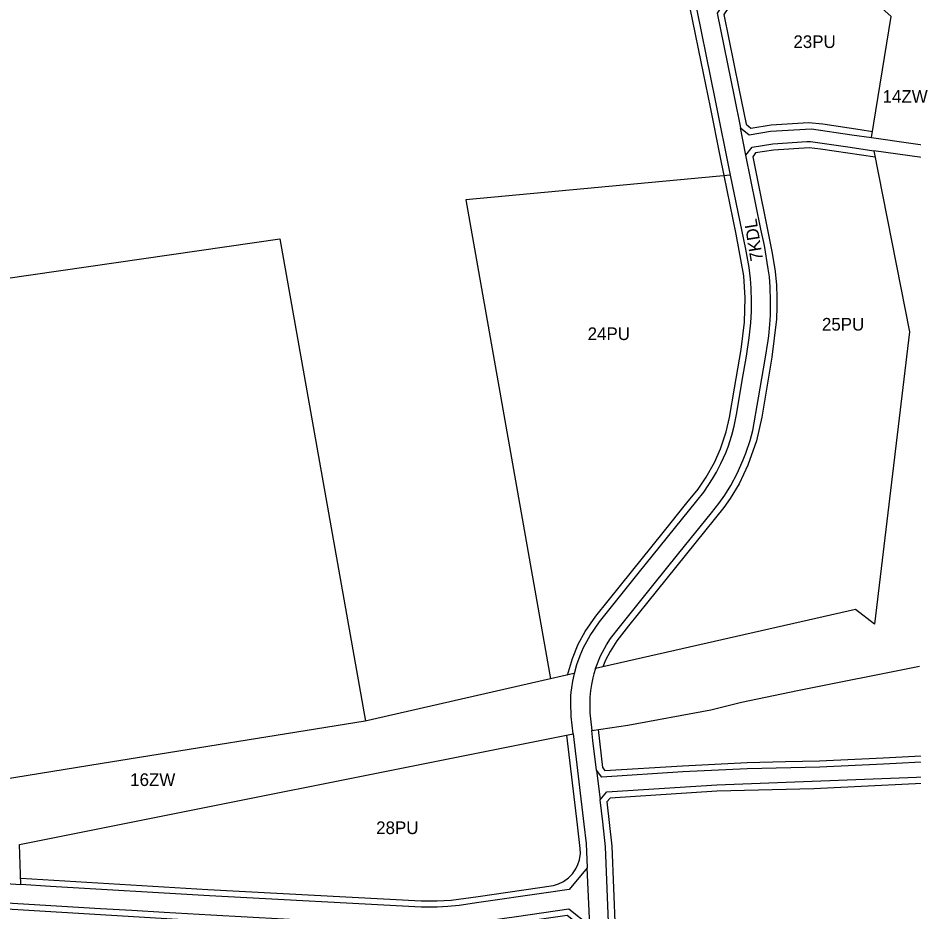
# Model space of a CAD drawing. Extents: x 7428203 to 7432868, y 5542672 to 5545406.
# Drawn here: x 7429895 to 7430602, y 5543859 to 5544564 of the extents above; entities that cross this region are included whole.
import ezdxf

# ---------------------------------------------------------------- set-up
doc = ezdxf.new("R2010")
doc.units = 0
for name, color, linetype in [('linie_rozgraniczajace', 7, 'Continuous'), ('linie_zabudowy_nieprzekraczalne', 7, 'Continuous'), ('oznaczenia_przeznaczen', 7, 'Continuous')]:
    doc.layers.add(name, color=color, linetype=linetype)

msp = doc.modelspace()

# ---------------------------------------------------------------- linework, layer by layer
at = {"layer": 'linie_rozgraniczajace'}
for p, q in [((7430635.44, 5544449.92), (7430571.27, 5544459.14)), ((7430571.27, 5544459.14), (7430599.39, 5544316.2)), ((7430599.39, 5544316.2), (7430571.63, 5544085.3)), ((7430556.6, 5544096.8), (7430351.39, 5544050.23)), ((7430571.63, 5544085.3), (7430556.6, 5544096.8)), ((7430351.39, 5544050.23), (7430350.06, 5544045.98)), ((7430510.83, 5544032.94), (7430607.17, 5544051.99)), ((7430349.25, 5544042.86), (7430348.11, 5544037.51)), ((7430350.06, 5544045.98), (7430349.25, 5544042.86)), ((7430348.11, 5544037.51), (7430347.39, 5544032.85)), ((7430346.86, 5544027.65), (7430346.66, 5544022.69)), ((7430347.39, 5544032.85), (7430346.86, 5544027.65)), ((7430466.5, 5544023.7), (7430510.83, 5544032.94)), ((7430346.66, 5544022.69), (7430346.83, 5544015.27)), ((7430442.42, 5544017.56), (7430466.5, 5544023.7)), ((7430346.83, 5544015.27), (7430347.24, 5544010.35)), ((7430376.69, 5544005.34), (7430442.42, 5544017.56)), ((7430347.24, 5544010.35), (7430348.32, 5544001.36)), ((7430348.32, 5544001.36), (7430376.69, 5544005.34)), ((7430349.26, 5543993.46), (7430348.32, 5544001.36)), ((7430352.08, 5543970), (7430349.26, 5543993.46)), ((7430471.2, 5543970.94), (7430420.25, 5543968.49)), ((7430528.46, 5543972.27), (7430471.2, 5543970.94)), ((7430578.76, 5543974.63), (7430528.46, 5543972.27)), ((7430631.1, 5543977.3), (7430578.76, 5543974.63)), ((7430356.31, 5543964.43), (7430352.08, 5543970)), ((7430352.08, 5543970), (7430354.92, 5543946.37)), ((7430420.25, 5543968.49), (7430356.31, 5543964.43)), ((7430447, 5543958.42), (7430641.3, 5543965.87)), ((7430360.29, 5543952.75), (7430447, 5543958.42)), ((7430354.92, 5543946.37), (7430360.29, 5543952.75)), ((7430357, 5543929.02), (7430354.92, 5543946.37)), ((7430359.23, 5543909.49), (7430357, 5543929.02)), ((7430361.88, 5543843.19), (7430359.23, 5543909.49))]:
    msp.add_line(p, q, dxfattribs=at)
for points in [[(7430457.97, 5544439.94), (7430446.05, 5544498.9), (7430427.95, 5544588.48), (7430420.35, 5544625.11)], [(7430470.09, 5544455.7), (7430465.74, 5544477.21), (7430472.67, 5544471.8), (7430489.65, 5544474.52), (7430521.79, 5544476.48), (7430553.88, 5544471.74), (7430569.42, 5544469.51), (7430584.87, 5544565.16), (7430563.07, 5544584.92), (7430554.24, 5544583.75), (7430532.74, 5544581.22), (7430519.71, 5544580.53), (7430493.95, 5544579.21), (7430453.82, 5544577.48), (7430447.41, 5544567.9), (7430460.75, 5544501.87), (7430465.74, 5544477.21)], [(7430351.39, 5544050.23), (7430355.34, 5544060.32), (7430359.99, 5544068.89), (7430363.09, 5544073.8), (7430370.17, 5544082.89), (7430396.63, 5544115.75), (7430417.17, 5544141.27), (7430442.92, 5544173.26), (7430448.83, 5544180.6), (7430453.44, 5544187.22), (7430458.17, 5544194.87), (7430463.17, 5544204.14), (7430468.02, 5544214.93), (7430470.1, 5544220.23), (7430473.42, 5544230.29), (7430475.46, 5544238.15), (7430480.04, 5544263.9), (7430485.31, 5544294.55), (7430487.59, 5544309.3), (7430488.1, 5544313.04), (7430489, 5544321.97), (7430489.45, 5544329.17), (7430489.61, 5544335.11), (7430489.63, 5544340.5), (7430489.24, 5544351.51), (7430488.61, 5544359.44), (7430487.81, 5544365.89), (7430484.66, 5544384.16), (7430481.93, 5544397.12), (7430470.09, 5544455.7), (7430475.05, 5544462.06), (7430491.42, 5544464.62), (7430518.2, 5544466.48), (7430521.12, 5544466.48), (7430552.43, 5544461.85), (7430571.27, 5544459.14)], [(7430569.42, 5544469.51), (7430633.38, 5544460.3)], [(7430334.65, 5544046.29), (7430336.64, 5544053.5), (7430339.05, 5544060.42), (7430341.77, 5544066.74), (7430346.97, 5544076.34), (7430354.31, 5544087.15), (7430384.94, 5544125.16), (7430431.24, 5544182.66), (7430436.82, 5544189.6), (7430440.93, 5544195.5), (7430443.69, 5544199.89), (7430446.9, 5544205.38), (7430448.26, 5544207.93), (7430450.4, 5544212.15), (7430452.42, 5544216.56), (7430454.14, 5544220.61), (7430455.99, 5544225.32), (7430459.03, 5544234.53), (7430460.84, 5544241.52), (7430462.71, 5544250.78), (7430465.24, 5544266.38), (7430467.2, 5544277.74), (7430470.5, 5544296.91), (7430472.75, 5544311.46), (7430474.05, 5544323.19), (7430474.54, 5544332.24), (7430474.63, 5544340.19), (7430474.27, 5544350.65), (7430473.69, 5544357.92), (7430472.56, 5544367.02), (7430469.94, 5544381.26), (7430457.97, 5544439.94), (7430248.78, 5544420.45), (7430315.6, 5544041.93)], [(7429810.29, 5543885.43), (7429897.37, 5543879.68), (7429896.16, 5543911.28), (7430333.54, 5543998.57), (7430332, 5544012.38), (7430331.66, 5544022.98), (7430331.89, 5544028.62), (7430332.14, 5544031.45), (7430332.52, 5544034.83), (7430333.36, 5544040.22), (7430334.65, 5544046.29), (7430334.23, 5544046.17), (7430315.6, 5544041.93), (7430169.18, 5544008.59), (7429959.79, 5543974.93), (7429805.3, 5543949.82)], [(7430333.54, 5543998.57), (7430342.1, 5543927.28), (7430343.85, 5543911.94), (7430344.79, 5543892.69), (7430330.57, 5543875.57), (7430310.52, 5543872.69), (7430259.19, 5543865.33), (7430243.57, 5543863.06), (7430234.64, 5543862.21), (7430226.25, 5543861.71), (7430213.4, 5543861.63), (7430046.22, 5543870.69), (7429920.63, 5543878), (7429897.37, 5543879.68)], [(7429692.68, 5543891.06), (7429733.68, 5543881.76), (7429787.12, 5543873.02), (7429851.1, 5543867.29), (7429960.09, 5543860.73), (7429984.9, 5543859.31), (7430010.49, 5543857.85), (7430047.45, 5543855.75), (7430162.05, 5543849.26), (7430213.06, 5543846.63), (7430226.75, 5543846.71), (7430245.5, 5543848.19), (7430288.91, 5543854.44), (7430330.3, 5543860.39), (7430346.69, 5543847.34), (7430344.79, 5543892.69)]]:
    msp.add_lwpolyline(points, dxfattribs=at)
at = {"layer": 'linie_zabudowy_nieprzekraczalne'}
for p, q in [((7429885.23, 5544358.31), (7430101.92, 5544389.47)), ((7430101.92, 5544389.47), (7430169.6, 5544008.69)), ((7430353.27, 5544002.05), (7430356.88, 5543971.95)), ((7430528.31, 5543977.27), (7430578.52, 5543979.63)), ((7430578.52, 5543979.63), (7430660.3, 5543983.98)), ((7430356.88, 5543971.95), (7430358.67, 5543969.59)), ((7430358.67, 5543969.59), (7430419.97, 5543973.48)), ((7430419.97, 5543973.48), (7430471, 5543975.94)), ((7430471, 5543975.94), (7430501.45, 5543976.84)), ((7430501.45, 5543976.84), (7430528.31, 5543977.27))]:
    msp.add_line(p, q, dxfattribs=at)
for points in [[(7430452.96, 5544439.48), (7430449.8, 5544455.13), (7430442.03, 5544493.58), (7430434.78, 5544529.46), (7430415.09, 5544626.01)], [(7430567.92, 5544580.53), (7430542.08, 5544577.28), (7430529.17, 5544576.02), (7430511.85, 5544575.12), (7430456.57, 5544572.6), (7430452.66, 5544566.75), (7430464.55, 5544508.32), (7430470.27, 5544480.01), (7430474.03, 5544477.08), (7430489.96, 5544479.56), (7430519.47, 5544481.48), (7430530.94, 5544480.24), (7430560.29, 5544475.87), (7430570.21, 5544474.44)], [(7430520.1, 5544461.48), (7430491.98, 5544459.65), (7430477.78, 5544457.43), (7430475.44, 5544454.44), (7430490.83, 5544378.22), (7430493.13, 5544363.66), (7430494.14, 5544353.06), (7430494.53, 5544343.5), (7430494.61, 5544335.77), (7430494.27, 5544326.12), (7430490.61, 5544296.21), (7430482.65, 5544248.81), (7430478.48, 5544229.89), (7430471.7, 5544210.79), (7430464.65, 5544196.18), (7430457.58, 5544184.42), (7430452.55, 5544177.25), (7430392.7, 5544102.9), (7430377.35, 5544083.83), (7430368.08, 5544072.13), (7430362.82, 5544063.77), (7430359.23, 5544056.71), (7430357.03, 5544051.51)], [(7430572.29, 5544453.94), (7430528.96, 5544460.32), (7430520.1, 5544461.48)], [(7430329.27, 5544045.04), (7430332.97, 5544058.17), (7430337.6, 5544069.56), (7430342.97, 5544079.41), (7430351.44, 5544091.54), (7430371.01, 5544115.81), (7430404.6, 5544157.55), (7430423.43, 5544180.94), (7430432.3, 5544191.95), (7430438.74, 5544201.41), (7430445.23, 5544212.97), (7430450.01, 5544223.76), (7430454.54, 5544237.14), (7430457.12, 5544248.36), (7430461.06, 5544271.56), (7430466.22, 5544302.18), (7430469.07, 5544323.69), (7430469.53, 5544343.01), (7430468.34, 5544360.41), (7430462.3, 5544393.27), (7430452.96, 5544439.48)], [(7429897.18, 5543884.71), (7430044.87, 5543875.77), (7430213.51, 5543866.63), (7430226.09, 5543866.71), (7430237.27, 5543867.38), (7430258.48, 5543870.28), (7430317.97, 5543878.91), (7430322.02, 5543880.16), (7430325.94, 5543882.1), (7430329.96, 5543885.01), (7430333.01, 5543888.15), (7430335.73, 5543892.05), (7430337.37, 5543895.47), (7430338.56, 5543899.11), (7430339.33, 5543904.11), (7430339.28, 5543907.95), (7430337.14, 5543926.7), (7430328.62, 5543997.64)], [(7431096.64, 5543746.01), (7431141.07, 5543916.56), (7431154.13, 5543968.32), (7431158.32, 5543987.8), (7431156.03, 5543991.21), (7431112.21, 5543991.77), (7431069.72, 5543992.03), (7431019.7, 5543990.63), (7430951.97, 5543986.06), (7430719.62, 5543965.92), (7430641.58, 5543960.87), (7430523.7, 5543955.12), (7430447.22, 5543953.43), (7430362.74, 5543947.9), (7430360.14, 5543944.81), (7430364.22, 5543909.88), (7430366.87, 5543843.51)], [(7430352.56, 5543805.37), (7430345.56, 5543820.39), (7430342.81, 5543831.42), (7430341.79, 5543844.85), (7430328.95, 5543855.08), (7430246.14, 5543843.23), (7430226.91, 5543841.71), (7430212.94, 5543841.63), (7430161.78, 5543844.27), (7430047.23, 5543850.54), (7429850.78, 5543862.3), (7429817.78, 5543864.62), (7429787.47, 5543867.62), (7429750.04, 5543873.61), (7429700.15, 5543884.05)]]:
    msp.add_lwpolyline(points, dxfattribs=at)

# ---------------------------------------------------------------- texts
at = {"layer": 'oznaczenia_przeznaczen'}
for s, p in [('23PU', (7430507.6228, 5544540.25)), ('14ZW', (7430578.0633, 5544497)), ('25PU', (7430530.1728, 5544317.1)), ('24PU', (7430345.0528, 5544309.59)), ('16ZW', (7429983.6333, 5543957.43)), ('28PU', (7430177.9728, 5543919.43))]:
    msp.add_text(s, height=10, dxfattribs=at).set_placement(p)
msp.add_text('7KDL', height=10, rotation=99.199226, dxfattribs=at).set_placement((7430483.7454, 5544372.9018))

doc.saveas('drawing.dxf')
